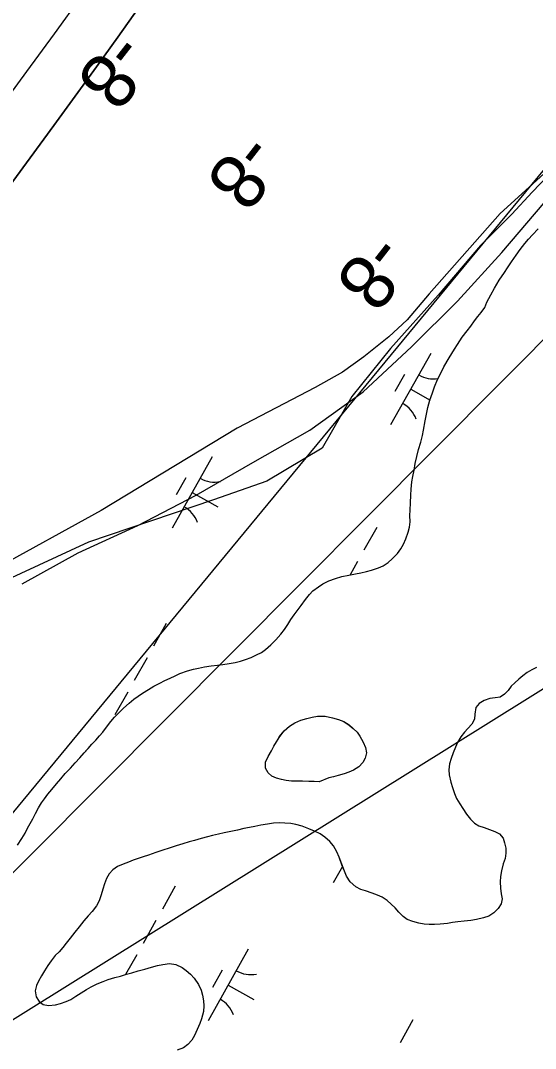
# Model space of a CAD drawing. Extents: x 3913936 to 3933962, y 195330 to 217741.
# Drawn here: x 3924433 to 3924747, y 201638 to 202265 of the extents above; entities that cross this region are included whole.
import ezdxf

# ---------------------------------------------------------------- set-up
doc = ezdxf.new("R2010")
doc.units = 0
for name, color, linetype in [('V-RIVR-EDGE', 7, 'Continuous'), ('V-RIVR-RANG', 7, 'Continuous'), ('V-RRAP-FSHR', 7, 'Continuous'), ('V-TOPO-DPTH', 7, 'Continuous'), ('V-TOPO-MINR', 7, 'Continuous'), ('V-TOPO-SHOR', 7, 'Continuous'), ('V-UTIL-LINE', 7, 'Continuous'), ('V-WETL-SWMP', 7, 'Continuous')]:
    doc.layers.add(name, color=color, linetype=linetype)

msp = doc.modelspace()

# ---------------------------------------------------------------- linework, layer by layer
at = {"layer": 'V-RIVR-EDGE'}
msp.add_lwpolyline([(3925098.63, 202758.93), (3925059.31, 202672.43), (3925011, 202591.54), (3924949.22, 202480.33), (3924880.69, 202352.26), (3924836.88, 202270.25), (3924817.78, 202251.15), (3924794.19, 202225.31), (3924775.09, 202191.61), (3924744.76, 202160.16), (3924732.4, 202146.67), (3924713.3, 202127.58), (3924687.46, 202097.24), (3924658.25, 202064.67), (3924634.66, 202035.46), (3924616.69, 202004), (3924582.99, 201983.78), (3924550.41, 201972.55), (3924474.02, 201946.71), (3924413.35, 201918.62), (3924368.42, 201893.91), (3924286.41, 201801.79), (3924186.42, 201686.08), (3924176.5, 201661.59)], dxfattribs=at)
at = {"layer": 'V-RRAP-FSHR'}
msp.add_lwpolyline([(3924433.68, 201921.2), (3924467.85, 201940.26), (3924504.26, 201956.84), (3924539.68, 201975.32), (3924574.43, 201995.15), (3924609.17, 202014.97), (3924641.62, 202038.3), (3924671.18, 202065.79), (3924699.23, 202093.6), (3924726.17, 202123.28), (3924752.16, 202153.55)], dxfattribs=at)
at = {"layer": 'V-TOPO-DPTH'}
msp.add_lwpolyline([(3924992.9, 203003.97), (3924555.02, 202345.74), (3924542.66, 202327.33), (3924530.18, 202308.99), (3924517.55, 202290.77), (3924504.81, 202272.62), (3924491.94, 202254.56), (3924479.01, 202236.54), (3924465.99, 202218.59), (3924452.9, 202200.69), (3924405, 202135.5), (3924367.96, 202085.01), (3924330.97, 202034.47), (3924294.08, 201983.86), (3924257.25, 201933.22), (3923922.06, 201471.51), (3923911.22, 201456.61), (3923900.34, 201441.72), (3923889.44, 201426.86), (3923878.5, 201412.02), (3923708.45, 201181.75), (3923640.5, 201090.06), (3923572.36, 200998.52), (3923503.91, 200907.2)], dxfattribs=at)
at = {"layer": 'V-TOPO-MINR'}
for points in [[(3923351.01, 200825.4), (3923855.49, 201471.09), (3923855.91, 201471.62), (3923857.21, 201473.18), (3923858.1, 201474.21), (3923858.54, 201474.73), (3923858.97, 201475.25), (3923902.56, 201527.46), (3923924.57, 201554.26), (3923946.3, 201581.29), (3923967.61, 201608.64), (3923988.63, 201636.23), (3924419.72, 202211.03), (3924436.57, 202233.72), (3924453.27, 202256.52), (3924469.75, 202279.48), (3924486.09, 202302.55), (3924557.12, 202403.88), (3924608.45, 202477.97), (3924659.22, 202552.44), (3924709.16, 202627.47), (3924758.55, 202702.87), (3924974.34, 203036.37)], [(3923503.91, 200907.2), (3923572.36, 200998.52), (3923640.5, 201090.06), (3923708.45, 201181.75), (3923878.5, 201412.02), (3923889.44, 201426.86), (3923900.34, 201441.72), (3923911.22, 201456.61), (3923922.06, 201471.51), (3924257.25, 201933.22), (3924294.08, 201983.86), (3924330.97, 202034.47), (3924367.96, 202085.01), (3924405, 202135.5), (3924452.9, 202200.69), (3924465.99, 202218.59), (3924479.01, 202236.54), (3924491.94, 202254.56), (3924504.81, 202272.62), (3924517.55, 202290.77), (3924530.18, 202308.99), (3924542.66, 202327.33), (3924555.02, 202345.74), (3924992.9, 203003.97)]]:
    msp.add_lwpolyline(points, dxfattribs=at)
at = {"layer": 'V-TOPO-SHOR'}
for points in [[(3924735.04, 202121.74), (3924737.54, 202125.12), (3924740.3, 202128.77), (3924742.54, 202131.46), (3924745.04, 202134.14), (3924748.49, 202137.79)], [(3924495.46, 201845.42), (3924499, 201848.46), (3924501.84, 201850.89), (3924504.43, 201852.89), (3924506.94, 201854.62), (3924510.65, 201856.89), (3924513.94, 201858.8), (3924517.65, 201860.62), (3924520.76, 201862.36), (3924523.87, 201863.76), (3924526.9, 201865.15), (3924529.83, 201866.54), (3924534.5, 201868.2), (3924538.22, 201869.25), (3924541.16, 201869.95), (3924544.79, 201870.65), (3924548.85, 201871.27), (3924552.75, 201871.71), (3924556.12, 201872.15), (3924560.01, 201872.68), (3924563.64, 201873.3), (3924566.84, 201874.17), (3924569.95, 201875.05), (3924573.24, 201876.35), (3924576.61, 201877.92), (3924579.54, 201879.49), (3924582.05, 201881.22), (3924585.33, 201884.09), (3924588.35, 201887.21), (3924591.45, 201890.59), (3924593.7, 201893.46), (3924595.68, 201896.4), (3924597.57, 201899.52), (3924599.55, 201902.38), (3924601.36, 201904.9), (3924603.78, 201908.11), (3924606.45, 201911.74), (3924608.86, 201914.69), (3924610.93, 201916.95), (3924614.39, 201919.47), (3924616.98, 201921.29), (3924620.69, 201923.12), (3924624.84, 201924.6), (3924628.65, 201925.65), (3924632.88, 201926.62), (3924636.95, 201927.32), (3924640.32, 201928.02), (3924643.78, 201928.81), (3924646.81, 201929.6), (3924651.04, 201930.99), (3924653.89, 201932.3), (3924656.83, 201934.21), (3924659.42, 201936.46), (3924662.61, 201939.76), (3924664.59, 201942.62), (3924666.31, 201945.48), (3924667.69, 201948.77), (3924669.06, 201952.76), (3924669.92, 201955.79), (3924670.26, 201958.99), (3924670.16, 201962.88), (3924670.32, 201966.26), (3924670.48, 201970.67), (3924670.82, 201975.43), (3924670.89, 201978.89), (3924671.31, 201983.48), (3924671.91, 201986.77), (3924672.68, 201990.58), (3924673.45, 201994.65), (3924674.38, 201998.98), (3924675.5, 202003.22), (3924676.78, 202007.72), (3924677.81, 202011.62), (3924678.49, 202014.99), (3924679.52, 202020.62), (3924680.2, 202023.74), (3924681.14, 202028.76), (3924682.42, 202033.26), (3924683.88, 202037.76), (3924685.25, 202041.4), (3924687.06, 202045.82), (3924688.35, 202048.59), (3924690.93, 202053.61), (3924694.03, 202059.07), (3924697.3, 202064.27), (3924699.2, 202067.22), (3924702.13, 202071.56), (3924705.06, 202075.46), (3924707.3, 202078.4), (3924709.63, 202081.53), (3924711.7, 202084.21), (3924713.59, 202086.73), (3924715.92, 202089.68), (3924717.21, 202092.97), (3924719.53, 202097.56), (3924721.77, 202101.46), (3924724.7, 202106.4), (3924727.89, 202111.17), (3924729.7, 202113.94), (3924732.19, 202117.67), (3924735.04, 202121.74)], [(3924747.47, 201870.36), (3924744.56, 201868.9), (3924741.66, 201867.23), (3924739.17, 201865.25), (3924736.58, 201863.07), (3924734.1, 201860.88), (3924731.92, 201858.8), (3924730.17, 201856.3), (3924727.89, 201853.91), (3924725.19, 201852.24), (3924722.19, 201851.71), (3924718.86, 201851.28), (3924715.44, 201850.24), (3924712.44, 201848.26)], [(3924430.8, 201762.01), (3924433.38, 201766.08), (3924435.36, 201769.29), (3924436.83, 201772.24), (3924438.55, 201775.18), (3924440.1, 201778.04), (3924441.82, 201781.25), (3924443.54, 201784.63), (3924445.35, 201787.75), (3924447.16, 201790.26), (3924449.31, 201793.04), (3924451.73, 201795.98), (3924454.49, 201799.28), (3924457.16, 201802.49), (3924459.92, 201805.7), (3924463.03, 201808.91), (3924465.96, 201812.12), (3924468.81, 201815.24), (3924471.39, 201818.19), (3924473.81, 201820.88), (3924476.22, 201823.56), (3924478.47, 201825.91), (3924480.79, 201828.51), (3924482.78, 201830.85), (3924485.02, 201833.88), (3924487.78, 201837.27), (3924490.02, 201840.04), (3924492.78, 201842.73), (3924495.46, 201845.42)], [(3924712.44, 201848.26), (3924710.37, 201845.86), (3924709.86, 201841.81), (3924709.66, 201838.7), (3924707.9, 201835.68), (3924705.52, 201833.08), (3924703.45, 201830.89), (3924701.17, 201828.08), (3924699.21, 201824.55), (3924697.97, 201821.64), (3924696.53, 201818.31), (3924695.29, 201814.78), (3924694.37, 201811.45), (3924693.96, 201807.82), (3924694.18, 201804.81), (3924695.13, 201800.45), (3924696.07, 201797.13), (3924697.43, 201793.5), (3924698.58, 201790.49), (3924700.56, 201787.17), (3924702.44, 201784.27), (3924704.73, 201780.75), (3924707.13, 201777.85), (3924709.63, 201775.36), (3924712.33, 201773.81), (3924715.45, 201772.78), (3924718.77, 201771.55), (3924721.89, 201770.31), (3924724.91, 201768.76), (3924726.99, 201766.28), (3924727.94, 201763.27), (3924728.67, 201760.05), (3924728.78, 201757.04), (3924728.27, 201753.82), (3924727.14, 201750.6), (3924726.01, 201746.23), (3924725.5, 201742.81)], [(3924614.87, 201800.57), (3924611.68, 201800.73), (3924608.57, 201800.72), (3924604.6, 201800.89), (3924601.15, 201800.96), (3924597.96, 201800.87), (3924594.68, 201801.29), (3924591.75, 201801.97), (3924588.81, 201802.74), (3924585.87, 201804.02), (3924583.62, 201806.09), (3924582.06, 201808.85), (3924582.14, 201812.47), (3924583.77, 201816.1), (3924585.74, 201819.47), (3924587.2, 201822.23), (3924588.75, 201824.91), (3924590.73, 201828.11), (3924593.48, 201831.65), (3924596.66, 201834.42), (3924600.02, 201836.5), (3924603.72, 201838.07), (3924607.26, 201839.2), (3924610.53, 201840.07), (3924613.9, 201840.68), (3924618.39, 201840.52), (3924623.04, 201839.67), (3924626.58, 201838.65), (3924629.78, 201837.28), (3924633.06, 201835.22), (3924635.57, 201833.15), (3924637.91, 201830.83), (3924639.73, 201828.33), (3924641.72, 201824.71), (3924643.11, 201821.44), (3924643.73, 201818.34), (3924642.96, 201815.05), (3924641.5, 201812.29), (3924639, 201809.61), (3924635.73, 201807.7), (3924632.97, 201806.48), (3924630.13, 201805.44), (3924626.51, 201804.4), (3924623.58, 201803.7), (3924620.65, 201803), (3924614.87, 201800.57)], [(3924725.5, 201742.81), (3924725.2, 201739.69), (3924725.42, 201735.75), (3924725.94, 201732.32), (3924726.47, 201729.21), (3924725.86, 201726.09), (3924724, 201723.39), (3924721.3, 201720.68), (3924718.3, 201718.7), (3924714.98, 201717.65), (3924710.83, 201716.6), (3924707.41, 201716.07), (3924703.25, 201715.65), (3924699.41, 201715.22), (3924696.2, 201714.8), (3924693.08, 201714.16), (3924688.72, 201713.84), (3924685.19, 201713.52), (3924681.97, 201713.62), (3924678.86, 201713.81), (3924675.64, 201714.43), (3924672, 201715.35), (3924668.57, 201716.59), (3924665.97, 201718.55), (3924663.37, 201721.14), (3924661.18, 201723.73), (3924658.79, 201726.01), (3924656.29, 201728.29), (3924653.27, 201730.25), (3924650.36, 201731.49), (3924647.14, 201732.62), (3924643.09, 201734.07), (3924640.18, 201734.99), (3924637.27, 201736.64), (3924633.83, 201739.54), (3924631.44, 201742.96), (3924630.18, 201746.18), (3924628.71, 201750.01), (3924626.94, 201754.68), (3924625.58, 201757.79), (3924623.6, 201761.63), (3924621.41, 201764.21), (3924618.29, 201766.91), (3924615.37, 201768.77), (3924611.94, 201770.42), (3924608.51, 201771.97), (3924604.35, 201773.51), (3924600.62, 201774.54), (3924597.6, 201775.16), (3924593.97, 201775.46), (3924590.33, 201775.65), (3924587.01, 201775.44), (3924583.27, 201774.8), (3924579.33, 201774.07), (3924575.49, 201773.33), (3924572.27, 201772.7), (3924568.95, 201772.06), (3924565.01, 201771.12), (3924560.86, 201770.28), (3924556.81, 201769.44), (3924553.49, 201768.7), (3924549.76, 201767.75), (3924546.75, 201767.02), (3924542.91, 201766.07), (3924538.76, 201764.82)], [(3924538.76, 201764.82), (3924535.44, 201763.98), (3924531.6, 201762.72), (3924527.56, 201761.46), (3924523.31, 201760.21), (3924519.36, 201758.84), (3924515.21, 201757.48), (3924510.65, 201755.91), (3924507.54, 201754.87), (3924504.43, 201753.92), (3924501.31, 201752.77), (3924498.41, 201751.62), (3924495.2, 201750.37), (3924491.88, 201748.9), (3924488.98, 201746.82), (3924486.7, 201744.53), (3924485.05, 201741.72), (3924483.81, 201738.39), (3924482.88, 201735.07), (3924481.75, 201731.64), (3924480.52, 201728.01), (3924478.96, 201724.99), (3924476.28, 201721.56), (3924473.9, 201718.95), (3924471.21, 201715.73), (3924468.31, 201712.19), (3924465.72, 201708.96), (3924462.83, 201705.22), (3924460.45, 201702.3), (3924458.48, 201699.6), (3924456.1, 201697), (3924453.82, 201694.6), (3924451.23, 201691.38), (3924449.27, 201688.57), (3924447.2, 201685.24), (3924445.45, 201682.33), (3924443.69, 201679.11)], [(3924443.69, 201679.11), (3924442.45, 201676.3), (3924441.53, 201673.08), (3924442.26, 201669.44), (3924444.04, 201666.54), (3924446.53, 201664.78), (3924449.65, 201664.27), (3924454.01, 201664.7), (3924457.02, 201665.44), (3924460.55, 201666.59), (3924463.34, 201667.84), (3924466.35, 201669.82), (3924469.56, 201671.91), (3924472.88, 201673.99), (3924475.78, 201675.66), (3924479.41, 201677.33), (3924483.04, 201678.8), (3924486.05, 201679.95), (3924490.09, 201681.21), (3924493.52, 201682.05), (3924497.25, 201683.2), (3924500.57, 201684.14), (3924504.31, 201685.3), (3924508.56, 201686.45), (3924512.61, 201687.6), (3924516.13, 201688.55), (3924519.35, 201689.28), (3924523.61, 201689.71), (3924527.45, 201689.1), (3924531.19, 201687.45), (3924533.69, 201685.58), (3924536.39, 201683.21), (3924538.48, 201680.93), (3924541.19, 201677.09), (3924542.75, 201673.57), (3924543.7, 201670.56), (3924544.23, 201667.13), (3924544.55, 201664.02), (3924544.35, 201660.59), (3924543.12, 201656.12), (3924541.98, 201653.21), (3924540.33, 201649.47), (3924538.78, 201645.94), (3924537.23, 201643.13), (3924534.75, 201640.42), (3924531.95, 201638.44), (3924528.22, 201636.98)]]:
    msp.add_lwpolyline(points, dxfattribs=at)
at = {"layer": 'V-UTIL-LINE'}
for points in [[(3922259.35, 198607.65), (3922481.8, 198996.51), (3922891.23, 199568.37), (3923401.91, 200205.88), (3924391.34, 201632.88), (3925141.51, 202100.49), (3925635.89, 202689.84), (3926060.57, 203224.55), (3926266.36, 203722.12), (3926398.76, 204373.14), (3926759.45, 205211.96), (3927229.53, 206070.79), (3927602.51, 206766.2), (3928031.78, 207586.17)], [(3927650.36, 207012.75), (3925143.73, 202648.17), (3924419.49, 201771.61), (3924393.53, 201817.62)], [(3926953.75, 204871.69), (3926114.53, 203439.18), (3924358.1, 201675.2), (3923230.85, 203513.49)]]:
    msp.add_lwpolyline(points, dxfattribs=at)
at = {"layer": 'V-WETL-SWMP'}
for p, q in [((3924682.95, 202061.7), (3924658.44, 202018.12)), ((3924666.91, 202048.92), (3924661.03, 202038.46)), ((3924670.69, 202039.91), (3924682.44, 202033.31)), ((3924549.58, 201998.74), (3924525.08, 201955.16)), ((3924533.54, 201985.96), (3924527.66, 201975.5)), ((3924537.33, 201976.95), (3924553.02, 201968.13)), ((3924650, 201955.72), (3924642.16, 201941.77)), ((3924638.24, 201934.8), (3924633.72, 201926.76)), ((3924521.57, 201897.14), (3924513.73, 201883.19)), ((3924509.81, 201876.22), (3924501.96, 201862.27)), ((3924498.04, 201855.3), (3924490.2, 201841.35)), ((3924629.1, 201748.99), (3924623.44, 201738.92)), ((3924527.03, 201736.96), (3924519.19, 201723.01)), ((3924515.26, 201716.04), (3924507.42, 201702.09)), ((3924503.5, 201695.12), (3924496.71, 201683.03)), ((3924571.6, 201698.48), (3924547.1, 201654.89)), ((3924555.57, 201685.69), (3924549.69, 201675.23)), ((3924559.35, 201676.68), (3924575.04, 201667.86)), ((3924672.02, 201655.45), (3924664.18, 201641.5))]:
    msp.add_line(p, q, dxfattribs=at)
for points in [[(3924800.9, 202215.84), (3924725.19, 202147.09), (3924681.95, 202098.18), (3924668.44, 202082.26), (3924657.24, 202071.77), (3924642.17, 202059.73), (3924629.03, 202050.4), (3924612.41, 202041.06), (3924564.85, 202016.14), (3924481.73, 201965.95), (3924416, 201929.76)], [(3924544.79, 201870.65), (3924548.85, 201871.27), (3924552.75, 201871.71), (3924556.12, 201872.15), (3924560.01, 201872.68), (3924563.64, 201873.3), (3924566.84, 201874.17), (3924569.95, 201875.05), (3924573.24, 201876.35), (3924576.61, 201877.92), (3924579.54, 201879.49), (3924582.05, 201881.22), (3924585.33, 201884.09), (3924588.35, 201887.21), (3924591.45, 201890.59), (3924593.7, 201893.46), (3924595.68, 201896.4), (3924597.57, 201899.52), (3924599.55, 201902.38), (3924601.36, 201904.9), (3924603.78, 201908.11), (3924606.45, 201911.75), (3924608.86, 201914.69), (3924610.93, 201916.95), (3924614.39, 201919.47), (3924616.98, 201921.29), (3924620.69, 201923.12), (3924624.84, 201924.6), (3924628.65, 201925.65), (3924632.88, 201926.61), (3924636.95, 201927.32), (3924640.32, 201928.02), (3924643.78, 201928.81), (3924646.81, 201929.6), (3924651.04, 201930.99), (3924653.89, 201932.3), (3924656.83, 201934.21), (3924659.42, 201936.46), (3924662.61, 201939.76), (3924664.59, 201942.62), (3924666.31, 201945.48), (3924667.69, 201948.77), (3924669.06, 201952.76), (3924669.92, 201955.79), (3924670.26, 201958.99), (3924670.16, 201962.88), (3924670.32, 201966.26), (3924670.48, 201970.67), (3924670.82, 201975.43), (3924670.89, 201978.89), (3924671.31, 201983.48), (3924671.91, 201986.77), (3924672.68, 201990.58), (3924673.45, 201994.65), (3924674.38, 201998.98), (3924675.5, 202003.22), (3924676.78, 202007.72), (3924677.81, 202011.62), (3924678.49, 202014.99), (3924679.52, 202020.62), (3924680.2, 202023.74), (3924681.14, 202028.76), (3924682.42, 202033.26), (3924683.88, 202037.76), (3924685.25, 202041.4), (3924687.06, 202045.82), (3924688.35, 202048.59), (3924690.93, 202053.61), (3924694.03, 202059.08), (3924697.3, 202064.27), (3924699.2, 202067.22), (3924702.13, 202071.56), (3924705.06, 202075.46), (3924707.3, 202078.41), (3924709.63, 202081.53), (3924711.7, 202084.21), (3924713.59, 202086.73), (3924715.92, 202089.68), (3924717.21, 202092.97), (3924719.53, 202097.56), (3924721.77, 202101.46), (3924724.7, 202106.4), (3924727.89, 202111.17), (3924729.7, 202113.94), (3924732.2, 202117.67), (3924735.04, 202121.74), (3924737.54, 202125.12), (3924740.3, 202128.77), (3924742.54, 202131.45), (3924745.04, 202134.14), (3924748.49, 202137.79)], [(3924430.8, 201762.01), (3924433.38, 201766.08), (3924435.36, 201769.29), (3924436.83, 201772.24), (3924438.55, 201775.18), (3924440.1, 201778.04), (3924441.82, 201781.25), (3924443.54, 201784.63), (3924445.35, 201787.75), (3924447.16, 201790.26), (3924449.31, 201793.04), (3924451.73, 201795.98), (3924454.49, 201799.28), (3924457.16, 201802.49), (3924459.92, 201805.7), (3924463.03, 201808.91), (3924465.96, 201812.12), (3924468.81, 201815.24), (3924471.39, 201818.19), (3924476.22, 201823.57), (3924478.47, 201825.91), (3924480.79, 201828.51), (3924482.78, 201830.85), (3924485.02, 201833.89), (3924487.78, 201837.27), (3924490.02, 201840.04), (3924492.78, 201842.73), (3924495.46, 201845.42), (3924499, 201848.46), (3924501.84, 201850.89), (3924504.43, 201852.89), (3924506.94, 201854.62), (3924510.65, 201856.89), (3924513.93, 201858.8), (3924517.65, 201860.62), (3924520.76, 201862.36), (3924523.87, 201863.76), (3924526.89, 201865.15), (3924529.83, 201866.54), (3924534.5, 201868.2), (3924538.22, 201869.25), (3924541.16, 201869.95), (3924544.79, 201870.65)], [(3924747.47, 201870.36), (3924744.56, 201868.9), (3924741.66, 201867.23), (3924739.17, 201865.25), (3924736.58, 201863.07), (3924734.1, 201860.88), (3924731.92, 201858.8), (3924730.17, 201856.3), (3924727.89, 201853.91), (3924725.19, 201852.24), (3924722.19, 201851.71), (3924718.86, 201851.29), (3924715.44, 201850.24), (3924712.44, 201848.26), (3924710.37, 201845.86), (3924709.86, 201841.81), (3924709.66, 201838.7), (3924707.9, 201835.68), (3924705.52, 201833.08), (3924703.45, 201830.89), (3924701.17, 201828.08), (3924699.21, 201824.55), (3924697.97, 201821.64), (3924696.53, 201818.31), (3924695.29, 201814.78), (3924694.37, 201811.45), (3924693.96, 201807.82), (3924694.18, 201804.81), (3924695.13, 201800.45), (3924696.07, 201797.13), (3924697.43, 201793.5), (3924698.58, 201790.49), (3924700.56, 201787.17), (3924702.44, 201784.27), (3924704.73, 201780.75), (3924707.13, 201777.85), (3924709.63, 201775.36), (3924712.33, 201773.81), (3924715.45, 201772.78), (3924718.77, 201771.55), (3924721.89, 201770.31), (3924724.91, 201768.76), (3924726.99, 201766.27), (3924727.93, 201763.27), (3924728.67, 201760.05), (3924728.78, 201757.04), (3924728.27, 201753.82), (3924727.14, 201750.6), (3924726.01, 201746.24), (3924725.5, 201742.81), (3924725.2, 201739.69), (3924725.42, 201735.75), (3924725.94, 201732.32), (3924726.47, 201729.21), (3924725.86, 201726.09), (3924724, 201723.39), (3924721.3, 201720.68), (3924718.3, 201718.7), (3924714.98, 201717.65), (3924710.83, 201716.6), (3924707.41, 201716.07), (3924703.25, 201715.65), (3924699.41, 201715.22), (3924696.2, 201714.8), (3924693.08, 201714.17), (3924688.72, 201713.84), (3924685.19, 201713.52), (3924681.97, 201713.61), (3924678.86, 201713.81), (3924675.64, 201714.43), (3924672, 201715.35), (3924668.57, 201716.59), (3924665.97, 201718.55), (3924663.37, 201721.14), (3924661.18, 201723.73), (3924658.79, 201726.01), (3924656.29, 201728.29), (3924653.27, 201730.25), (3924650.36, 201731.49), (3924647.14, 201732.62), (3924643.09, 201734.06), (3924640.18, 201734.99), (3924637.27, 201736.64), (3924633.83, 201739.54), (3924631.43, 201742.96), (3924630.18, 201746.18), (3924626.94, 201754.68), (3924625.58, 201757.79), (3924623.6, 201761.63), (3924621.41, 201764.22), (3924618.29, 201766.91), (3924615.37, 201768.77)], [(3924615.37, 201768.77), (3924611.94, 201770.42), (3924608.51, 201771.97), (3924604.35, 201773.51), (3924600.61, 201774.54), (3924597.6, 201775.15), (3924593.97, 201775.46), (3924590.33, 201775.65), (3924587.01, 201775.44), (3924583.27, 201774.8), (3924579.33, 201774.07), (3924575.49, 201773.33), (3924572.27, 201772.7), (3924568.96, 201772.06), (3924565.01, 201771.12), (3924560.86, 201770.28), (3924556.81, 201769.43), (3924553.49, 201768.7), (3924549.76, 201767.75), (3924546.75, 201767.02), (3924542.91, 201766.07), (3924538.76, 201764.82), (3924535.44, 201763.98), (3924531.6, 201762.72), (3924527.56, 201761.46), (3924523.31, 201760.21), (3924519.36, 201758.84), (3924515.21, 201757.48), (3924510.65, 201755.91), (3924507.54, 201754.87), (3924504.43, 201753.92), (3924501.31, 201752.77), (3924498.41, 201751.62), (3924495.2, 201750.37), (3924491.88, 201748.9), (3924488.98, 201746.82), (3924486.7, 201744.53), (3924485.04, 201741.72), (3924483.81, 201738.4), (3924482.88, 201735.07), (3924481.75, 201731.64), (3924480.52, 201728), (3924478.97, 201724.99), (3924476.28, 201721.55), (3924473.9, 201718.95), (3924471.21, 201715.73), (3924468.31, 201712.19), (3924465.72, 201708.96), (3924462.83, 201705.22), (3924460.45, 201702.3), (3924458.48, 201699.6), (3924456.1, 201697), (3924453.82, 201694.6), (3924451.23, 201691.38), (3924449.27, 201688.57), (3924447.2, 201685.24), (3924445.45, 201682.33), (3924443.69, 201679.1), (3924442.45, 201676.3), (3924441.53, 201673.08), (3924442.26, 201669.44), (3924444.04, 201666.54), (3924446.53, 201664.78), (3924449.65, 201664.27), (3924454.01, 201664.7), (3924457.02, 201665.44), (3924460.54, 201666.59), (3924463.34, 201667.84), (3924466.35, 201669.82), (3924469.56, 201671.91), (3924472.88, 201673.99), (3924475.78, 201675.66), (3924479.41, 201677.33), (3924483.04, 201678.8), (3924486.05, 201679.95), (3924490.09, 201681.21), (3924493.52, 201682.05), (3924497.25, 201683.2), (3924500.57, 201684.14), (3924504.31, 201685.3), (3924508.56, 201686.45), (3924512.61, 201687.6), (3924516.13, 201688.55), (3924519.35, 201689.28), (3924523.6, 201689.71), (3924527.45, 201689.1), (3924531.19, 201687.45), (3924533.69, 201685.58), (3924536.39, 201683.2), (3924538.48, 201680.93), (3924541.19, 201677.09), (3924542.75, 201673.57), (3924543.7, 201670.56), (3924544.23, 201667.13), (3924544.55, 201664.02), (3924544.35, 201660.59), (3924543.11, 201656.12), (3924541.98, 201653.21), (3924540.33, 201649.47), (3924538.78, 201645.94), (3924537.23, 201643.13)], [(3924537.23, 201643.13), (3924534.75, 201640.42), (3924531.95, 201638.44), (3924528.22, 201636.98)]]:
    msp.add_lwpolyline(points, dxfattribs=at)
msp.add_lwpolyline([(3924614.87, 201800.57), (3924611.68, 201800.73), (3924608.57, 201800.72), (3924604.6, 201800.89), (3924601.15, 201800.96), (3924597.96, 201800.87), (3924594.68, 201801.29), (3924591.75, 201801.97), (3924588.81, 201802.74), (3924585.87, 201804.02), (3924583.62, 201806.09), (3924582.06, 201808.85), (3924582.14, 201812.47), (3924583.77, 201816.1), (3924585.74, 201819.47), (3924587.2, 201822.23), (3924588.75, 201824.91), (3924590.72, 201828.11), (3924593.48, 201831.65), (3924596.66, 201834.42), (3924600.02, 201836.5), (3924603.72, 201838.07), (3924607.26, 201839.2), (3924610.53, 201840.07), (3924613.9, 201840.68), (3924618.38, 201840.52), (3924623.04, 201839.67), (3924626.58, 201838.65), (3924629.78, 201837.28), (3924633.06, 201835.21), (3924635.57, 201833.15), (3924637.91, 201830.83), (3924639.73, 201828.33), (3924641.72, 201824.71), (3924643.11, 201821.44), (3924643.72, 201818.33), (3924642.96, 201815.05), (3924641.5, 201812.29), (3924639, 201809.61), (3924635.73, 201807.7), (3924632.97, 201806.49), (3924630.13, 201805.44), (3924626.51, 201804.4), (3924623.58, 201803.7), (3924620.65, 201803)], close=True, dxfattribs=at)
for centre, start, end in [((3924684.44, 202063.87), 239.88608, 279.59692), ((3924657.37, 202015.72), 19.88608, 61.42973), ((3924551.07, 202000.91), 239.88608, 281.42974), ((3924524, 201952.76), 19.88608, 61.42973), ((3924573.09, 201700.64), 239.88608, 281.42974), ((3924546.02, 201652.49), 19.88608, 61.42973)]:
    msp.add_arc(centre, 17.62, start, end, dxfattribs=at)

# ---------------------------------------------------------------- texts
at = {"layer": 'V-RIVR-RANG'}
for p in [(3924490.11, 202259.54), (3924569.08, 202198.2), (3924648.06, 202136.87)]:
    msp.add_text('-8', height=33.5, rotation=232.02833, dxfattribs=at).set_placement(p)

doc.saveas('drawing.dxf')
